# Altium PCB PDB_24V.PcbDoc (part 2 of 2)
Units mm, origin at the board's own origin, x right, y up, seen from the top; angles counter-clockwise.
Board outline 185 x 160 mm, 4 copper layers (Top Layer, Int1 (GND), Int2 (GND), Bottom Layer), stack 1.636 mm thick; 170 components, 90 nets, 598 pads, 1109 vias.
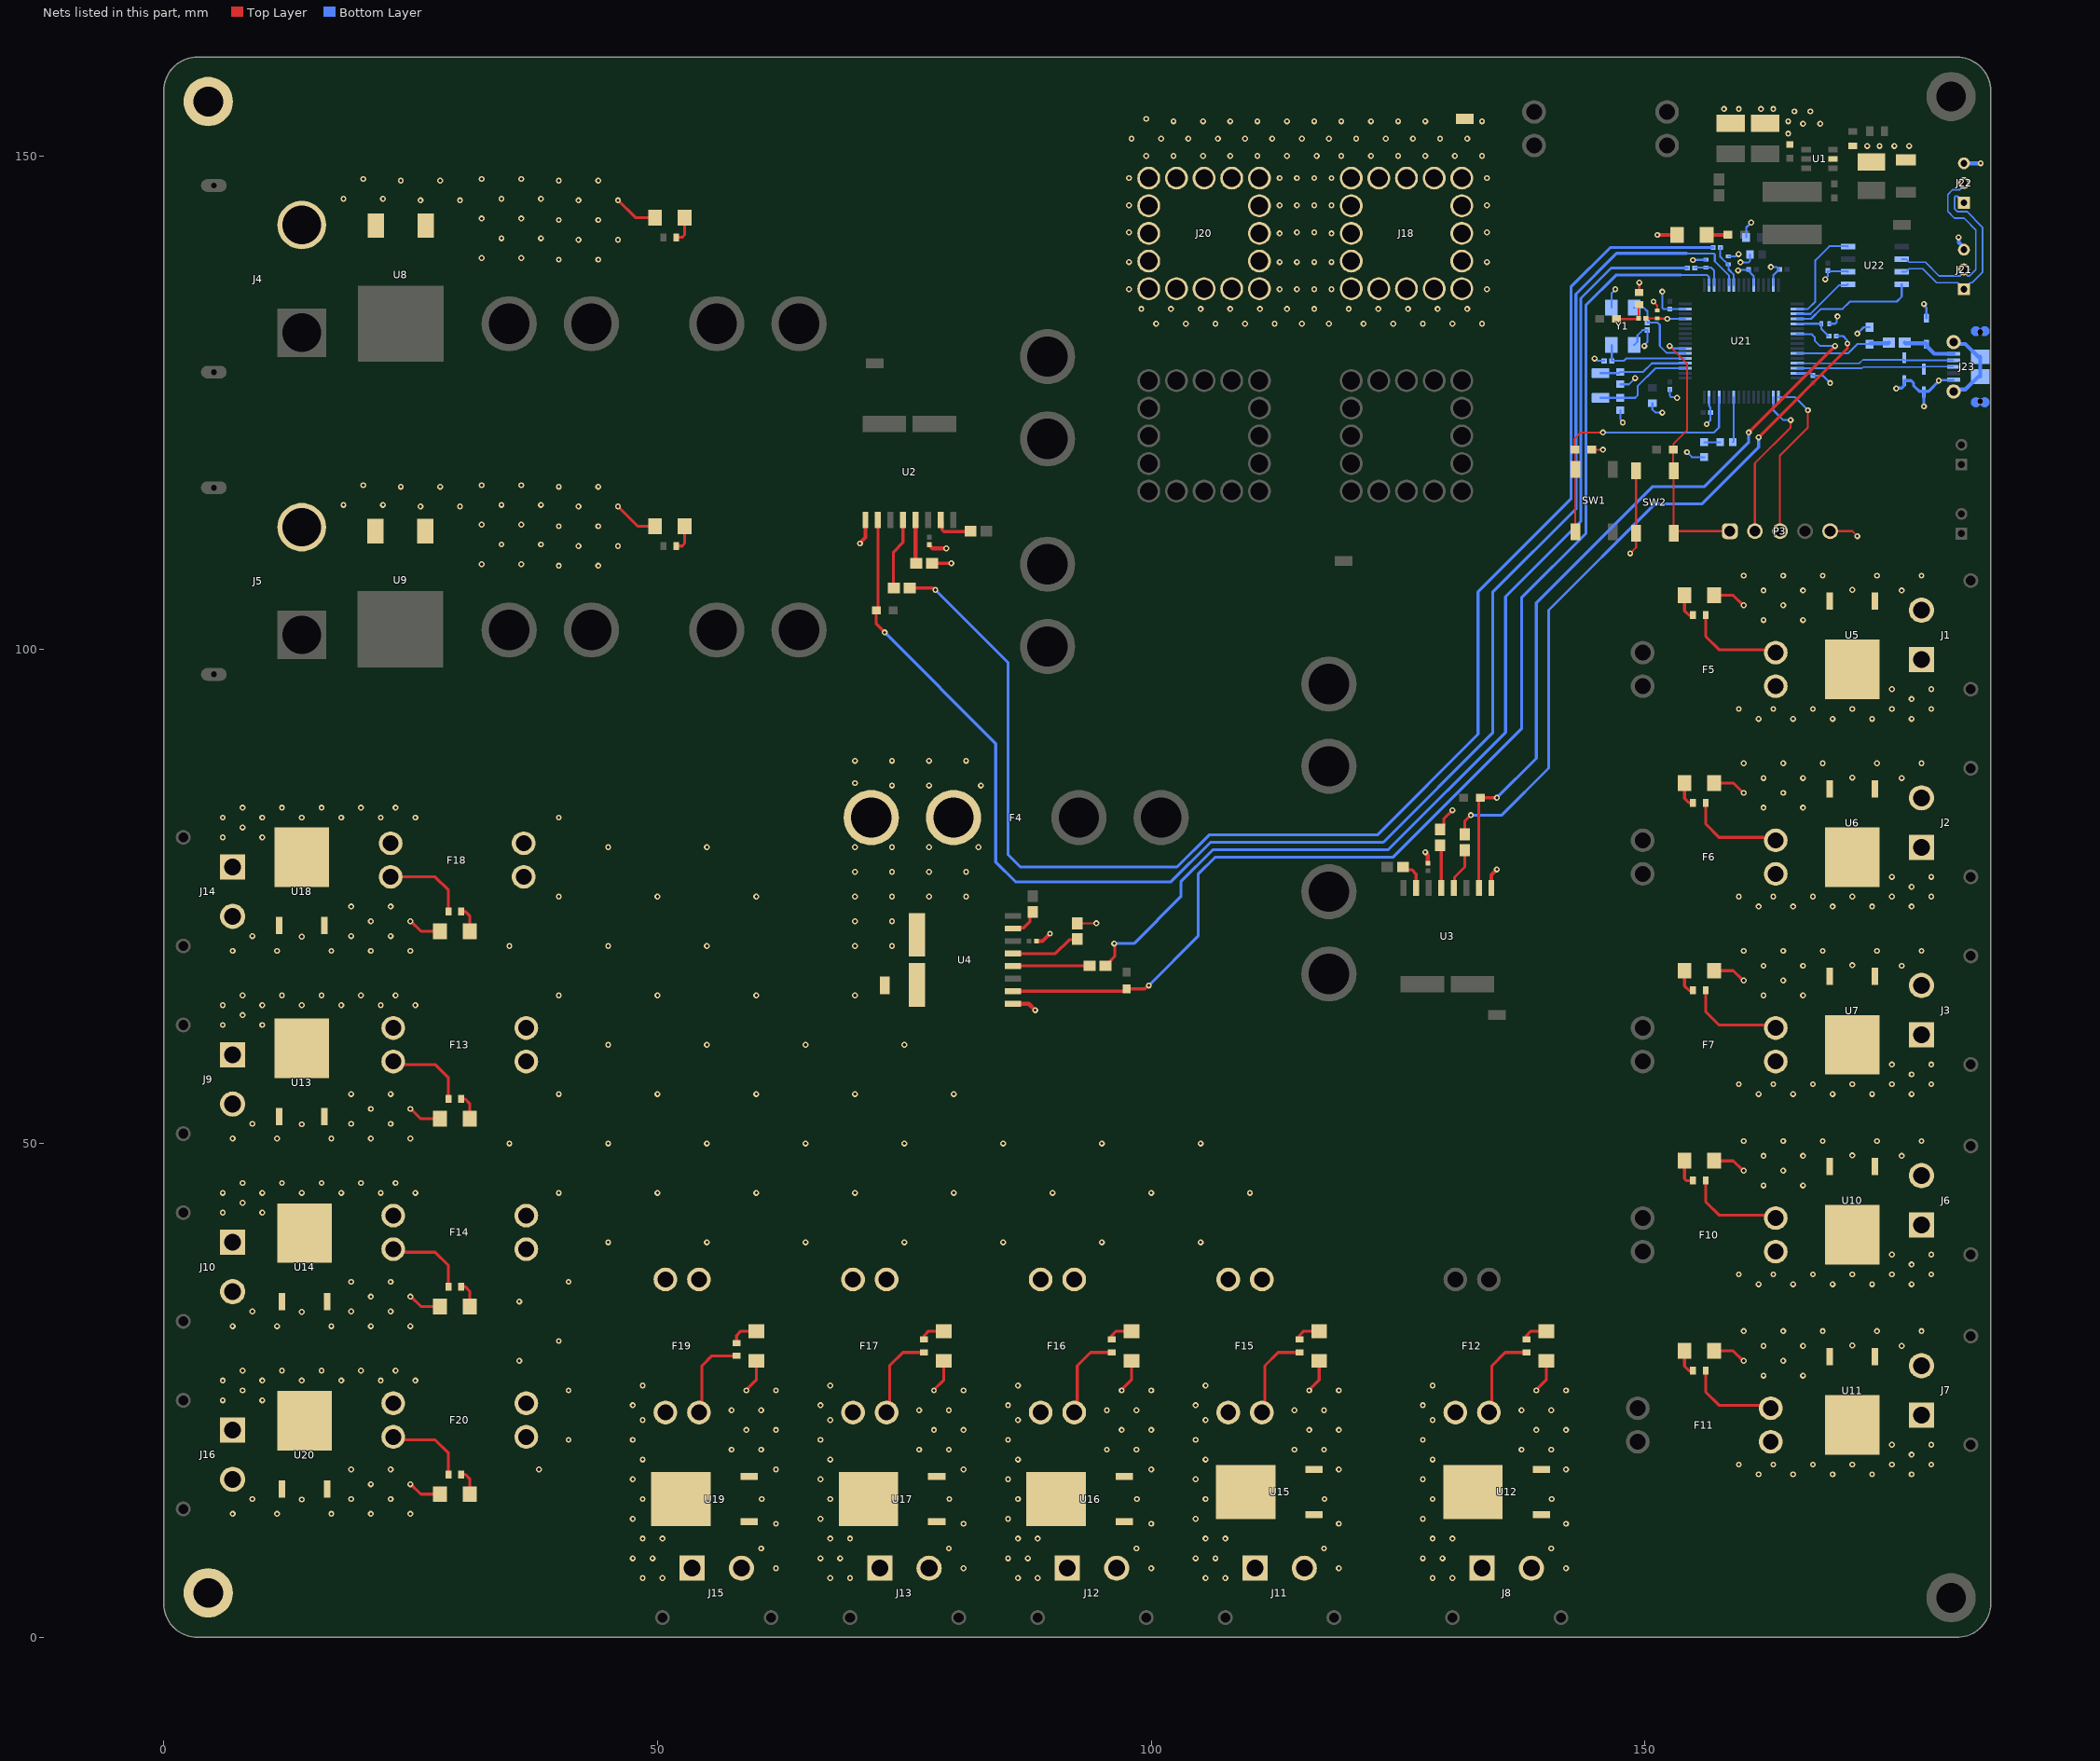
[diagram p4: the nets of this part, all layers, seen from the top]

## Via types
v1: diameter 0.6, hole 0.3, Top Layer to Bottom Layer, 1109 vias

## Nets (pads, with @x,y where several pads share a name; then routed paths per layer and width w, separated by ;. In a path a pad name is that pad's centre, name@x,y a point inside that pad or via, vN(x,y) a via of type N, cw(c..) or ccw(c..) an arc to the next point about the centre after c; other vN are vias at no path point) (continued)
24V_LIGTHING: F14.2_1 F14.2_2 J10.P R20.2 U14.3 | length 8.6
  Top Layer w0.3: F14.2_1@22.975,39 27.475,39 28.825,37.65 R20.2@28.825,35.5
  other v1: 5.975,43 9.975,43 7.975,44 5.975,45 9.975,45 13.975,45 17.975,45 21.975,45 25.475,45 7.975,46 11.975,46 15.975,46 19.975,46 23.475,46
24V_M0: F5.2_1 F5.2_2 J1.P R11.2 U5.3 | length 8.6
  Top Layer w0.3: R11.2@156.15,103.5 156.15,101.35 157.5,100 162,100
  other v1: 161.5,93 165,93 169,93 173,93 177,93 159.5,94 163,94 167,94 171,94 175,94 179,94 177,95 175,96 179,96
24V_M1: F6.2_1 F6.2_2 J2.P R12.2 U6.3 | length 8.6
  Top Layer w0.3: R12.2@156.15,84.5 156.15,82.35 157.5,81 162,81
  other v1: 161.5,74 165,74 169,74 173,74 177,74 159.5,75 163,75 167,75 171,75 175,75 179,75 177,76 175,77 179,77
24V_M2: F7.2_1 F7.2_2 J3.P R13.2 U7.3 | length 8.6
  Top Layer w0.3: R13.2@156.15,65.5 156.15,63.35 157.5,62 162,62
  other v1: 161.5,55 165,55 169,55 173,55 177,55 159.5,56 163,56 167,56 171,56 175,56 179,56 177,57 175,58 179,58
24V_M3: F10.2_1 F10.2_2 J6.P R16.2 U10.3 | length 8.6
  Top Layer w0.3: R16.2@156.15,46.25 156.15,44.1 157.5,42.75 162,42.75
  other v1: 161.5,35.75 165,35.75 169,35.75 173,35.75 177,35.75 159.5,36.75 163,36.75 167,36.75 171,36.75 175,36.75 179,36.75 177,37.75 175,38.75 179,38.75
24V_M4: F11.2_1 F11.2_2 J7.P R17.2 U11.3 | length 8.6
  Top Layer w0.3: R17.2@156.15,27 156.15,24.85 157.5,23.5 F11.2_1@162,23.5
  other v1: 161.5,16.5 165,16.5 169,16.5 173,16.5 177,16.5 159.5,17.5 163,17.5 167,17.5 171,17.5 175,17.5 179,17.5 177,18.5 175,19.5 179,19.5
24V_M5: F12.2_1 F12.2_2 J8.P R18.2 U12.3 | length 8.6
  Top Layer w0.3: F12.2_1@134.5,23 134.5,27.5 135.85,28.85 R18.2@138,28.85
  other v1: 128.5,6 130.5,6 127.5,8 129.5,8 128.5,10 130.5,10 127.5,12 128.5,14 127.5,16 128.5,18 127.5,20 128.5,22 127.5,23.5 128.5,25.5
24V_MISC_F: F4.2_1 F4.2_2 U4.1
  other v1: 70,70 73.75,70 70,72.5 73.75,72.5 70,75 73.75,75 77.5,75 81.25,75 70,77.5 73.75,77.5 77.5,77.5 81.25,77.5 70,80 73.75,80 77.5,80 82.5,80 73.75,86.25 77.5,86.25 82.75,86.25 70,86.5 70,88.75 73.75,88.75 77.5,88.75 81.25,88.75
24V_MISC_S: F13.1_1 F13.1_2 F14.1_1 F14.1_2 F15.1_1 F15.1_2 F16.1_1 F16.1_2 F17.1_1 F17.1_2 F18.1_1 F18.1_2 F19.1_1 F19.1_2 F20.1_1 F20.1_2 J29.1 U4.2
  other v1: 38,17 41,20 41,25 36,28 40,30 36,34 41,36 45,40 55,40 65,40 75,40 85,40 95,40 105,40 40,45 50,45 60,45 70,45 80,45 90,45 100,45 110,45 35,50 45,50 55,50 65,50 75,50 85,50 95,50 105,50 40,55 50,55 60,55 70,55 80,55 45,60 55,60 65,60 75,60 40,65 50,65 60,65 70,65 35,70 45,70 55,70 40,75 50,75 60,75 45,80 55,80 40,83
24V_PoE: F18.2_1 F18.2_2 J14.P R24.2 U18.3 | length 8.6
  Top Layer w0.3: F18.2_1@22.975,77 27.475,77 28.825,75.65 R24.2@28.825,73.5
  other v1: 5.975,81 9.975,81 7.975,82 5.975,83 9.975,83 13.975,83 17.975,83 21.975,83 25.475,83 7.975,84 11.975,84 15.975,84 19.975,84 23.475,84
24V_SCIENCE: F13.2_1 F13.2_2 J9.P R19.2 U13.3 | length 8.6
  Top Layer w0.3: F13.2_1@22.975,58 27.475,58 28.825,56.65 R19.2@28.825,54.5
  other v1: 5.975,62 9.975,62 7.975,63 5.975,64 9.975,64 13.975,64 17.975,64 21.975,64 25.475,64 7.975,65 11.975,65 15.975,65 19.975,65 23.475,65
24V_SPARE_1: F15.2_1 F15.2_2 J11.P R21.2 U15.3 | length 8.6
  Top Layer w0.3: F15.2_1@111.5,23 111.5,27.5 112.85,28.85 R21.2@115,28.85
  other v1: 105.5,6 107.5,6 104.5,8 106.5,8 105.5,10 107.5,10 104.5,12 105.5,14 104.5,16 105.5,18 104.5,20 105.5,22 104.5,23.5 105.5,25.5
24V_SPARE_2: F16.2_1 F16.2_2 J12.P R22.2 U16.3 | length 8.6
  Top Layer w0.3: F16.2_1@92.5,23 92.5,27.5 93.85,28.85 R22.2@96,28.85
  other v1: 86.5,6 88.5,6 85.5,8 87.5,8 86.5,10 88.5,10 85.5,12 86.5,14 85.5,16 86.5,18 85.5,20 86.5,22 85.5,23.5 86.5,25.5
24V_SPARE_3: F17.2_1 F17.2_2 J13.P R23.2 U17.3 | length 8.6
  Top Layer w0.3: F17.2_1@73.5,23 73.5,27.5 74.85,28.85 R23.2@77,28.85
  other v1: 67.5,6 69.5,6 66.5,8 68.5,8 67.5,10 69.5,10 66.5,12 67.5,14 66.5,16 67.5,18 66.5,20 67.5,22 66.5,23.5 67.5,25.5
24V_SPARE_4: F19.2_1 F19.2_2 J15.P R25.2 U19.3 | length 8.3
  Top Layer w0.3: F19.2_1@54.5,23 54.5,27.5 55.5,28.5 R25.2@57.903,28.5
  other v1: 48.5,6 50.5,6 47.5,8 49.5,8 48.5,10 50.5,10 47.5,12 48.5,14 47.5,16 48.5,18 47.5,20 48.5,22 47.5,23.5 48.5,25.5
24V_SPARE_5: F20.2_1 F20.2_2 J16.P R26.2 U20.3 | length 8.6
  Top Layer w0.3: F20.2_1@22.975,20 27.475,20 28.825,18.65 R26.2@28.825,16.5
  other v1: 5.975,24 9.975,24 7.975,25 5.975,26 9.975,26 13.975,26 17.975,26 21.975,26 25.475,26 7.975,27 11.975,27 15.975,27 19.975,27 23.475,27
ARM_ALERT: R5.1 U2.4 U21.22 | length 164.5
  Top Layer w0.3: U2.4@72.325,113.125 72.325,104.175 R5.1@72.15,104 72.15,102.6 v1(73,101.75)
  Bottom Layer w0.2: 154.2,140.125 156.958,140.125 157.075,140.008 157.075,139.325 158.5,137.9 U21.22@158.5,136.924
  Bottom Layer w0.3: v1(73,101.75) 84.25,90.5 84.25,78.5 86.25,76.5 102,76.5 106,80.5 123.5,80.5 134.575,91.575 134.575,105.825 143,114.25 143,136 147.125,140.125 154.2,140.125
ARM_SENSE: R7.2 R34.1 | length 150.9
  Top Layer w0.3: R7.2@76.051,106.25 77.868,106.25 78.06,106.057 v1(78.142,106.057)
  Bottom Layer w0.3: v1(78.142,106.057) 85.5,98.699 85.5,79.25 86.75,78 102.597,78 105.847,81.25 122.896,81.25 133.1,91.454 133.1,105.85 142.5,115.25 142.5,136.725 146.5,140.725 R34.1@156.9,140.725
ARM_SENSE_IN: C26.2 R34.2 U21.23 | length 4.4
  Bottom Layer w0.2: R34.2@157.65,140.725 157.625,140.7 157.625,139.776 158.076,139.325 158.1,139.325 158.4,139.025 C26.2@158.45,139.025 ; C26.2@158.375,139 158.466,138.909 158.466,138.5 159,137.966 U21.23@159,136.924
B3.3V_LED: D1.2 R2.2 | length 2.1
  Top Layer w0.4: D1.2@156.25,142 R2.2@158.4,142
B24_Voltage: C27.2 R36.2 U21.13 | length 4
  Top Layer w0.2: R36.2@150.1,133.55 C27.2@151.243,133.55 151.268,133.525 152.241,133.525 v1(152.265,133.501)
  Bottom Layer w0.2: v1(152.265,133.501) U21.13@154.076,133.501
B24_Voltage_In: R35.1 R36.1 R37.2 | length 3.7
  Top Layer w0.2: R35.1@147.1,133.475 R36.1@149.275,133.475 ; R36.1@149.35,133.55 R37.2@149.35,134.875 ; R36.1@149.4,133.475 R36.1@149.475,133.55 ; R37.2@149.425,134.925 R37.2@149.475,134.875
CAN_N: J21.2 J22.2 U22.6 | length 20.7
  Bottom Layer w0.172: U22.6@176,139.54 176.451,139.54 176.644,139.346 176.644,139.342 176.745,139.241 178.39,139.241 179.795,137.836 181.893,137.836 J21.2@182.3,138.242 ; J21.2@182.3,138.5 J21.2@182.3,138.242 ; J22.2@182.3,147.25 182.3,146.992 181.893,146.586 181.164,146.586 180.67,146.092 180.67,144.366 181.343,143.692 182.308,143.692 183.5,142.5 183.5,138.487 182.849,137.836 182.707,137.836 J21.2@182.3,138.242
CAN_P: J21.1 J22.1 U22.7 | length 20.6
  Bottom Layer w0.172: U22.7@176,138.27 176.451,138.27 176.644,138.464 176.644,138.468 176.745,138.569 178.112,138.569 179.517,137.164 181.685,137.164 181.786,137.063 181.786,137.014 J21.1@182.3,136.5 182.814,137.014 182.814,137.063 182.915,137.164 183.127,137.164 184.172,138.209 184.172,142.778 182.586,144.364 181.621,144.364 181.342,144.644 181.342,145.813 181.442,145.914 181.685,145.914 181.786,145.813 181.786,145.764 J22.1@182.3,145.25
CAN_RX: U21.34 U22.4 | length 10.2
  Bottom Layer w0.2: U21.34@165.424,134.501 166.501,134.501 167.25,135.25 167.25,139.434 168.666,140.85 170.512,140.85 U22.4@170.552,140.81
CAN_STB: U21.36 U22.8 | length 12.8
  Bottom Layer w0.2: U21.36@165.424,133.501 166.816,133.501 167.816,134.5 170,134.5 170.75,135.25 175.5,135.25 176,135.75 U22.8@176,137
CAN_TX: U21.35 U22.1 | length 6.4
  Bottom Layer w0.2: U21.35@165.424,134.001 166.751,134.001 169.639,136.889 170.44,136.889 U22.1@170.552,137
CHASSIS_ALERT: R6.1 U3.4 U21.39 | length 78.4
  Top Layer w0.3: U3.4@133.175,75.875 133.175,84.825 R6.1@133.35,85 v1(135,85) ; v1(160.5,122) v1(169.25,130.75)
  Bottom Layer w0.2: U21.39@165.424,132 165.464,131.96 166.091,131.96 166.112,131.94 166.877,131.94 167.184,131.633 167.184,131.316 167.75,130.75 v1(169.25,130.75)
  Bottom Layer w0.3: v1(135,85) 139,89 139,104.75 150.75,116.5 156,116.5 160.5,121 v1(160.5,122)
CHASSIS_SENSE: R8.2 R33.1 | length 72
  Top Layer w0.3: R8.2@131.75,81.301 131.75,82.635 v1(132.365,83.25) ; v1(161.5,121.5) 170.5,130.5 v1(170.5,131)
  Bottom Layer w0.2: R33.1@169.375,131.75 170.075,131.75 170.443,131.382 170.443,131.057 v1(170.5,131)
  Bottom Layer w0.3: v1(132.365,83.25) 135.5,83.25 140.25,88 140.25,104 151,114.75 155.75,114.75 161.5,120.5 v1(161.5,121.5)
CHASSIS_SENSE_IN: C25.2 R33.2 U21.37 | length 4
  Bottom Layer w0.2: U21.37@165.424,133 167.85,133 167.85,132.5 168.6,131.75 R33.2@168.625,131.75
GND: C2.2 C3.2 C4.1 C5.1 C6.1 C7.1 C8.1 C9.1 C10.1 C11.1 C12.1 C13.1 C14.1 C15.1 C16.1 C17.1 C18.1 C19.1 C20.1 C21.1 C22.1 C23.1 C24.1 C25.1 C26.1 C27.1 D1.1 D2.1 D3.1 D4.1 D5.1 D6.1 D7.1 D8.1 D9.1 D10.1 D11.1 D12.1 D13.1 D14.1 D15.1 D16.1 D17.1 D18.1 D19.2 J1.N J2.N J3.N J4.N J5.N J6.N J7.N J8.N J9.N J10.N J11.N J12.N J13.N J14.N J15.N J16.N J18.1 J18.2 J18.3 J18.4 J18.5 J18.6 J18.7 J18.8 J18.9 J18.10 J18.11 J18.12 J18.13 J18.14 J18.15 J18.16 J20.1 J20.2 J20.3 J20.4 J20.5 J20.6 J20.7 J20.8 J20.9 J20.10 J20.11 J20.12 J20.13 J20.14 J20.15 J20.16 J21.3 J22.3 J23.5 J23.6 J23.7 J23.8 J23.9 J23.10 J23.11 J25.1 P3.5 pad.2@4.5,4.5 pad.2@4.5,155.5 R4.2 R29.1 R31.1 R37.1 R38.2 R39.2 R42.2 SW2.1 SW2.2 U1.2 U2.3 U3.3 U4.3 U5.1 U5.2 U6.1 U6.2 U7.1 U7.2 U8.1 U8.2 U9.1 U9.2 U10.1 U10.2 U11.1 U11.2 U12.1 U12.2 U13.1 U13.2 U14.1 U14.2 U15.1 U15.2 U16.1 U16.2 U17.1 U17.2 U18.1 U18.2 U19.1 U19.2 U20.1 U20.2 U21.15 U21.27 U21.31 U21.47 U21.63 U22.2 U23.2 U24.2 Y1.2 Y1.4 | length 158.5
  Top Layer w0.2: R42.2@92.5,72.301 v1(94.449,72.301) ; R29.1@144.6,120.25 v1(145.75,120.25) ; v1(148.5,109.75) 149.1,110.35 SW2.1@149.1,111.8 SW2.2@149.1,118.1 ; R37.1@149.425,136.175 v1(149.425,137.175) ; v1(150.868,135.25) 150.868,135.225 151.243,134.85 C27.1@151.243,134.35 ; P3.5@168.75,112 171,112 v1(171.5,111.5)
  Top Layer w0.3: v1(24.975,15.5) 25.036,15.5 26.036,14.5 D17.1@27.975,14.5 ; v1(24.975,34.5) 25.036,34.5 26.036,33.5 D11.1@27.975,33.5 ; v1(24.975,53.5) 25.036,53.5 26.036,52.5 D10.1@27.975,52.5 ; v1(24.975,72.5) 25.036,72.5 26.036,71.5 D15.1@27.975,71.5 ; v1(46,114.5) 48,112.5 D6.1@49.75,112.5 ; v1(46,145.5) 47.75,143.75 D5.1@49.75,143.75 ; v1(59,25) 59,25.061 60,26.061 D16.1@60,28 ; R38.2@77.801,108.75 v1(79.75,108.75) ; v1(78,25) 78,25.061 79,26.061 D14.1@79,28 ; v1(97,25) 97,25.061 98,26.061 D13.1@98,28 ; v1(116,25) 116,25.061 117,26.061 D12.1@117,28 ; R39.2@129.25,81.801 129.629,82.18 129.629,82.879 v1(130.5,83.75) ; v1(139,25) 139,25.061 140,26.061 D9.1@140,28 ; D8.1@157,29 158.939,29 v1@159.939,28 ; D7.1@157,48.25 158.939,48.25 159.939,47.25 v1(160,47.25) ; D4.1@157,67.5 158.939,67.5 159.939,66.5 v1(160,66.5) ; D3.1@157,86.5 158.939,86.5 v1@159.939,85.5 ; D2.1@157,105.5 158.939,105.5 v1@159.939,104.5 ; v1@159.939,28 v1(160,28) v1@159.939,28 ; v1@159.939,85.5 v1(160,85.5) v1@159.939,85.5 ; v1@159.939,104.5 v1(160,104.5) v1@159.939,104.5
  Top Layer w0.4: v1(70.5,110.75) 70.5,110.804 71.055,111.359 U2.3@71.055,113.125 ; C7.1@77.5,110.621 77.5,110.6 77.536,110.564 77.558,110.564 77.871,110.25 v1(79.25,110.25) ; U4.3@86,64.15 87.6,64.15 v1(88.25,63.5) ; C9.1@88.379,70.5 89,70.5 v1(89.75,71.25) ; v1(127.75,79.5) 127.75,79.446 128,79.196 C8.1@128,78.379 ; U3.3@134.445,75.875 134.445,77.195 v1(135,77.75) ; v1(151.25,142) D1.1@153.25,142
  Bottom Layer w0.2: v1(144.9,129.475) 145.008,129.475 145.233,129.25 C18.1@145.86,129.25 ; Y1.4@146.6,134.65 146.6,136.051 147,136.451 v1(147,136.5) ; C20.1@147.5,124.246 147.5,123.358 147.75,123.108 v1(147.75,123) ; C19.1@147.5,126.873 148.373,126.873 v1(149,127.5) ; Y1.2@148.9,130.85 149.233,131.183 149.233,131.833 149.76,132.36 C17.1@150.25,132.36 150.25,131.176 149.933,130.858 v1(149.933,130.75) ; C11.1@150.75,124.975 150.75,124.325 151.05,124.025 151.725,124.025 v1(151.75,124) ; v1(151.75,136.25) 151.75,134.61 151.867,134.493 C16.1@152.5,134.493 152.504,134.497 154.072,134.497 U21.15@154.076,134.501 ; C12.1@152.5,126.348 152.5,125.724 152.65,125.574 153.176,125.574 v1(153.25,125.5) ; v1(154.25,120) 154.75,119.5 D18.1@156,119.5 ; v1(154.85,139.45) 154.875,139.475 156.15,139.475 C24.1@156.175,139.5 ; v1(156.25,122.841) 156.629,123.22 C13.1@156.629,124 156.629,124.536 156.499,124.666 U21.63@156.499,125.576 ; C26.1@158.45,139.825 159.192,139.825 159.417,140.05 v1(159.475,140.05) ; v1(159.425,138.4) 159.475,138.45 160.443,138.45 C23.1@160.493,138.5 ; v1(159.675,139.225) 160.508,139.225 160.625,139.342 C22.1@160.625,140 ; C21.1@160.25,141.75 160.25,142.75 v1(160.75,143.25) ; C23.1@160.514,138.5 160.651,138.364 160.651,138.181 160.868,137.964 160.883,137.964 161,137.847 U21.27@161,136.924 ; v1(162.75,138.75) 163.35,138.75 C15.1@163.6,138.5 ; U21.31@163.001,136.924 163.001,137.901 C15.1@163.6,138.5 ; C15.1@163.621,138.5 C15.1@163.6,138.5 ; U21.47@165.424,127.999 166.779,127.999 167,127.779 C14.1@167,127.757 167.993,127.757 v1(168.75,127) ; v1(168.25,137.5) 168.25,137.564 168.5,137.814 C10.1@168.5,138.371 168.551,138.321 170.501,138.321 U22.2@170.552,138.27 ; C25.1@168.65,133 169.25,133 169.423,133.173 169.423,133.673 v1(169.5,133.75) ; v1(171.5,132) 172.15,132.65 R31.1@172.75,132.65 ; v1(178.25,135) 178.25,134.892 178.5,134.642 D19.2@178.5,133.55 ; v1(179.75,127.25) 179.8,127.3 181.2,127.3 J23.5@181.25,127.35
  Bottom Layer w0.3: v1(175.44,126.44) 175.498,126.498 176.024,126.498 176.2,126.674 U23.2@176.2,126.895 ; U23.2@176.25,126.895 U23.2@176.25,127.25 176.95,127.25 177.203,126.997 177.203,126.732 177.775,126.16 178.2,126.16 U24.2@178.25,126.109 ; v1(178.25,124.627) U24.2@178.25,126.109 ; U24.2@178.25,126.1 U24.2@178.25,126.109 ; v1(179.75,127.25) 179.75,127.185 178.725,126.16 178.3,126.16 U24.2@178.25,126.109
  Bottom Layer w0.4: J23.7@181.25,126.15 181.451,126.351 182.451,126.351 183.75,127.65 J23.10@183.95,127.65 J23.9@183.95,129.65 183.75,129.65 182.451,130.949 181.451,130.949 J23.6@181.25,131.15 ; v1(181.75,141.75) 181.788,141.712 181.788,141.228 182.3,140.716 J21.3@182.3,140.5 ; J22.3@182.3,149.25 v1(184,149.25)
  other v1: 62,7 81,7 100,7 119,7 142,7 60.5,9 79.5,9 98.5,9 117.5,9 140.5,9 62,11.5 81,11.5 100,11.5 119,11.5 142,11.5 6.975,12.5 11.475,12.5 16.975,12.5 20.975,12.5 24.975,12.5 13.975,13.95 8.975,14 18.975,14 22.975,14 60.55,14 79.55,14 98.55,14 117.55,14 140.55,14 20.975,15.5 18.975,17 22.975,17 62,17 81,17 100,17 119,17 142,17 57.5,19 60.5,19 76.5,19 79.5,19 95.5,19 98.5,19 114.5,19 117.5,19 137.5,19 140.5,19 59,21 62,21 78,21 81,21 97,21 100,21 116,21 119,21 139,21 142,21 57.5,23 60.5,23 76.5,23 79.5,23 95.5,23 98.5,23 114.5,23 117.5,23 137.5,23 140.5,23 62,25 81,25 100,25 119,25 142,25 162,26.5 166,26.5 164,28 162,29.5 166,29.5 176,29.5 171,29.55 160,31 164,31 168,31 173.5,31 178,31 6.975,31.5 11.475,31.5 16.975,31.5 20.975,31.5 24.975,31.5 13.975,32.95 8.975,33 18.975,33 22.975,33 20.975,34.5 18.975,36 22.975,36 162,45.75 166,45.75 164,47.25 162,48.75 166,48.75 176,48.75 171,48.8 160,50.25 164,50.25 168,50.25 173.5,50.25 178,50.25 6.975,50.5 11.475,50.5 16.975,50.5 20.975,50.5 24.975,50.5 13.975,51.95 8.975,52 18.975,52 22.975,52 20.975,53.5 18.975,55 22.975,55 162,65 166,65 164,66.5 162,68 166,68 176,68 171,68.05 6.975,69.5 11.475,69.5 16.975,69.5 20.975,69.5 24.975,69.5 160,69.5 164,69.5 168,69.5 173.5,69.5 178,69.5 13.975,70.95 8.975,71 18.975,71 22.975,71 20.975,72.5 18.975,74 22.975,74 162,84 166,84 164,85.5 162,87 166,87 176,87 171,87.05 160,88.5 164,88.5 168,88.5 173.5,88.5 178,88.5 162,103 166,103 164,104.5 162,106 166,106 176,106 171,106.05 160,107.5 164,107.5 168,107.5 173.5,107.5 178,107.5 40,108.5 44,108.5 32.197,108.657 36.197,108.657 42,110.5 46,110.5 34.197,110.657 38.197,110.657 40,112.5 44,112.5 32.197,112.657 36.197,112.657 26,114.5 30,114.5 42,114.5 18.197,114.657 22.197,114.657 34.197,114.657 38.197,114.657 24,116.5 28,116.5 40,116.5 44,116.5 20.197,116.657 32.197,116.657 36.197,116.657 100.5,133 103.5,133 106.5,133 109.5,133 112.5,133 115.25,133 118,133 121.5,133 124.5,133 127.5,133 130.5,133 133.5,133 99,134.5 102,134.5 105,134.5 108,134.5 111,134.5 113.75,134.5 116.5,134.5 120,134.5 123,134.5 126,134.5 129,134.5 132,134.5 97.75,136.5 113,136.5 114.75,136.5 116.5,136.5 118.25,136.5 134,136.5 97.75,139.25 113,139.25 114.75,139.25 116.5,139.25 118.25,139.25 134,139.25 40,139.5 44,139.5 32.197,139.657 36.197,139.657 42,141.5 46,141.5 34.197,141.657 38.197,141.657 113,142.15 118.25,142.15 97.75,142.25 114.75,142.25 116.5,142.25 134,142.25 40,143.5 44,143.5 32.197,143.657 36.197,143.657 97.75,145 113,145 114.75,145 116.5,145 118.25,145 134,145 26,145.5 30,145.5 42,145.5 18.197,145.657 22.197,145.657 34.197,145.657 38.197,145.657 24,147.5 28,147.5 40,147.5 44,147.5 20.197,147.657 32.197,147.657 36.197,147.657 97.75,147.75 113,147.75 114.75,147.75 116.5,147.75 118.25,147.75 134,147.75 99.5,150 102.25,150 105.25,150 108,150 110.75,150 113.75,150 116.75,150 119.25,150 122.25,150 125,150 127.75,150 130.75,150 133.5,150 172.5,151 173.75,151 175.25,151 176.75,151 98,151.75 101,151.75 103.75,151.75 106.75,151.75 109.5,151.75 112.25,151.75 115.25,151.75 118,151.75 120.75,151.75 123.75,151.75 126.5,151.75 129.25,151.75 132,151.75 164.5,152.25 166,153.25 167.75,153.25 102.25,153.5 105.25,153.5 108,153.5 110.75,153.5 113.75,153.5 116.5,153.5 119.25,153.5 122.25,153.5 125,153.5 127.75,153.5 133.5,153.5 164.5,153.5 99.5,153.75 165.125,154.5 166.75,154.5 158,154.75 159.5,154.75 161.75,154.75 163,154.75
HSE_OSC_IN: C18.2 U21.5 Y1.3 | length 9.2
  Bottom Layer w0.2: Y1.3@146.6,130.85 146.64,130.81 C18.2@146.64,129.25 147.875,129.25 148.125,129.5 U21.5@154.076,129.5
HSE_OSC_OUT: C17.2 U21.6 Y1.1 | length 9
  Bottom Layer w0.2: Y1.1@148.9,134.65 149.85,134.65 150.25,134.25 C17.2@150.25,133.14 151.243,133.14 151.5,132.883 151.5,130.75 152.211,130.039 154.036,130.039 U21.6@154.076,130
LED_DEBUG_1: D18.2 R27.1 | length 1.6
  Bottom Layer w0.2: D18.2@156,121 R27.1@157.623,121
LED_DEBUG_2: R27.2 U21.58 | length 4.6
  Bottom Layer w0.2: R27.2@158.877,121 159,121.123 U21.58@159,125.576
LSE_OSC_IN: C20.2 U21.3 Y2.2 | length 10.4
  Bottom Layer w0.2: Y2.2@145.5,125.5 C20.2@147.5,125.5 149,125.5 149.25,125.75 149.25,126.689 151.061,128.499 U21.3@154.076,128.499
LSE_OSC_OUT: C19.2 U21.4 Y2.1 | length 9
  Bottom Layer w0.2: Y2.1@145.5,128 147.373,128 C19.2@147.5,128.127 149.811,128.127 150.684,128.999 U21.4@154.076,128.999
MCU_BOOT0: R29.2 SW1.1 SW1.2 U21.61 | length 27.6
  Top Layer w0.2: SW1.1@142.95,111.95 SW1.2@142.95,118.25 142.95,120.15 142.85,120.25 142.85,121.35 143.5,122 v1(145.75,122)
  Bottom Layer w0.2: v1(145.75,122) 157,122 157.499,122.499 U21.61@157.499,125.576
MCU_NRST: P3.1 R28.1 SW2.3 SW2.4 U21.7 | length 27.7
  Top Layer w0.2: v1(152.5,130.75) 154.251,128.999 154.251,122.201 152.883,120.833 152.883,120.283 R28.1@152.85,120.25 152.85,118.15 SW2.4@152.9,118.1 SW2.3@152.9,111.8 153.1,112 P3.1@158.59,112
  Bottom Layer w0.2: v1(152.5,130.75) 152.608,130.75 152.858,130.5 U21.7@154.076,130.5
MISC_ALERT: R9.1 U4.4 U21.18 | length 126.4
  Top Layer w0.3: U4.4@86,65.42 97.3,65.42 97.5,65.62 R9.1@97.5,65.65 99.346,65.65 99.696,66 v1(99.75,66)
  Bottom Layer w0.2: 153.625,137.925 156.3,137.925 156.483,137.742 156.483,136.94 U21.18@156.499,136.924
  Bottom Layer w0.3: v1(99.75,66) 104.75,71 104.75,77.25 106.5,79 124.5,79 137.5,92 137.5,105.25 144.025,111.775 144.025,134.899 147.051,137.925 153.625,137.925
MISC_SENSE: R10.2 R32.1 | length 111.3
  Top Layer w0.3: R10.2@95.352,68 95.426,68 95.805,68.379 95.805,68.453 96.307,68.955 96.307,70.193 v1(96.25,70.25)
  Bottom Layer w0.3: v1(96.25,70.25) 98.25,70.25 103,75 103,76.5 106.25,79.75 124,79.75 135.875,91.625 135.875,105.375 143.5,113 143.5,135.575 146.575,138.65 R32.1@154.3,138.65
MISC_SENSE_IN: C24.2 R32.2 U21.19 | length 3.6
  Bottom Layer w0.2: R32.2@155.05,138.65 155.075,138.675 156.15,138.675 C24.2@156.175,138.7 156.675,138.7 156.999,138.376 U21.19@156.999,136.924
NetD2_2: D2.2 R11.1 | length 2.6
  Top Layer w0.3: D2.2@154,105.5 154,103.95 154.45,103.5 R11.1@154.85,103.5
NetD3_2: D3.2 R12.1 | length 2.6
  Top Layer w0.3: D3.2@154,86.5 154,84.95 154.45,84.5 R12.1@154.85,84.5
NetD4_2: D4.2 R13.1 | length 2.6
  Top Layer w0.3: D4.2@154,67.5 154,65.95 154.45,65.5 R13.1@154.85,65.5
NetD5_2: D5.2 R14.1 | length 2.7
  Top Layer w0.3: R14.1@51.9,141.75 52.5,141.75 52.75,142 D5.2@52.75,143.75
NetD6_2: D6.2 R15.1 | length 2.7
  Top Layer w0.3: R15.1@51.9,110.5 52.5,110.5 52.75,110.75 D6.2@52.75,112.5
NetD7_2: D7.2 R16.1 | length 2.7
  Top Layer w0.3: D7.2@154,48.25 154,46.426 154.176,46.25 R16.1@154.85,46.25
NetD8_2: D8.2 R17.1 | length 2.6
  Top Layer w0.3: D8.2@154,29 154,27.45 154.45,27 R17.1@154.85,27
NetD9_2: D9.2 R18.1 | length 2.6
  Top Layer w0.3: R18.1@138,30.15 138,30.55 138.45,31 D9.2@140,31
NetD10_2: D10.2 R19.1 | length 2.6
  Top Layer w0.3: R19.1@30.125,54.5 30.525,54.5 30.975,54.05 D10.2@30.975,52.5
NetD11_2: D11.2 R20.1 | length 2.6
  Top Layer w0.3: R20.1@30.125,35.5 30.525,35.5 30.975,35.05 D11.2@30.975,33.5
NetD12_2: D12.2 R21.1 | length 2.6
  Top Layer w0.3: R21.1@115,30.15 115,30.55 115.45,31 D12.2@117,31
NetD13_2: D13.2 R22.1 | length 2.6
  Top Layer w0.3: R22.1@96,30.15 96,30.55 96.45,31 D13.2@98,31
NetD14_2: D14.2 R23.1 | length 2.6
  Top Layer w0.3: R23.1@77,30.15 77,30.55 77.45,31 D14.2@79,31
NetD15_2: D15.2 R24.1 | length 2.6
  Top Layer w0.3: R24.1@30.125,73.5 30.525,73.5 30.975,73.05 D15.2@30.975,71.5
NetD16_2: D16.2 R25.1 | length 2.9
  Top Layer w0.3: R25.1@58,29.792 58,30.55 58.45,31 D16.2@60,31
NetD17_2: D17.2 R26.1 | length 2.6
  Top Layer w0.3: R26.1@30.125,16.5 30.525,16.5 30.975,16.05 D17.2@30.975,14.5
NetR7_1: R7.1 U2.6 | length 7.3
  Top Layer w0.3: R7.1@73.898,106.25 73.898,109.898 74.865,110.865 U2.6@74.865,113.125
NetR8_1: R8.1 U3.6 | length 4.2
  Top Layer w0.3: U3.6@130.635,75.875 130.711,75.951 130.711,76.961 131.75,78 R8.1@131.75,79.564
NetR10_1: R10.1 U4.6 | length 7.8
  Top Layer w0.3: U4.6@86,67.96 86.02,67.98 R10.1@93.75,67.98
NetR38_1: R38.1 U2.7 | length 4.4
  Top Layer w0.4: U2.7@76.135,113.125 76.135,108.814 R38.1@76.199,108.75
NetR39_1: R39.1 U3.7 | length 4.3
  Top Layer w0.3: U3.7@129.365,75.875 R39.1@129.365,80.199
NetR40_2: R40.2 U2.9 | length 4
  Top Layer w0.3: U2.9@78.675,113.125 78.825,112.975 78.825,112.126 79.001,111.95 81.649,111.95 R40.2@81.699,112
NetR41_2: R41.2 U3.9 | length 3
  Top Layer w0.3: R41.2@125.5,78 125.774,77.726 126.377,77.726 126.825,77.278 U3.9@126.825,75.875
NetR42_1: R42.1 U4.7 | length 7.1
  Top Layer w0.3: U4.7@86,69.23 90.301,69.23 91.697,70.626 92.427,70.626 R42.1@92.5,70.699
NetR43_2: R43.2 U4.9 | length 3.1
  Top Layer w0.3: U4.9@86,71.77 86.078,71.848 87.084,71.848 87.726,72.49 87.726,73.175 R43.2@88,73.449
SWD_SWCLK: P3.2 U21.50 | length 16.2
  Top Layer w0.2: P3.2@161.13,112 161.13,118.88 164.75,122.5 v1(164.75,123.25)
  Bottom Layer w0.2: U21.50@163.001,125.576 163.001,124.249 164,123.25 v1(164.75,123.25)
SWD_SWDIO: P3.3 U21.49 | length 17
  Top Layer w0.2: P3.3@163.67,112 163.67,119.67 166.5,122.5 v1(166.5,124.25)
  Bottom Layer w0.2: U21.49@163.501,125.576 165.174,125.576 v1(166.5,124.25)
USB_D_N: J23.2 U21.45 U23.1 | length 16
  Bottom Layer w0.148: U21.45@165.424,128.999 171.714,128.999 172.064,129.35 174.25,129.35 176,129.35 176.25,129.35 176.3,129.3 176.5,129.3 176.75,129.3 J23.2@181.25,129.3
USB_D_P: J23.3 U21.46 U24.1 | length 15.9
  Bottom Layer w0.148: U21.46@165.424,128.499 171.964,128.499 172.065,128.6 178.25,128.6 178.3,128.65 J23.3@181.25,128.65
VBUS: D19.1 J23.1 R30.2 | length 5.6
  Bottom Layer w0.4: R30.2@176.301,131.1 176.376,131.025 178.45,131.025 178.5,130.975 D19.1@178.5,130.95 178.5,130.75 179.3,129.95 J23.1@181.25,129.95
VBUS_SENSE: R30.1 R31.2 U21.43 | length 9.7
  Bottom Layer w0.2: U21.43@165.424,130 170.55,130 171.5,130.95 R31.2@172.75,130.95 R31.2@172.825,131.025
  Bottom Layer w0.4: R31.2@172.825,131.025 174.624,131.025 R30.1@174.699,131.1
pads on no net: J1.S1 J1.S2 J2.S1 J2.S2 J3.S1 J3.S2 J4.S1 J4.S2 J5.S1 J5.S2 J6.S1 J6.S2 J7.S1 J7.S2 J8.S1 J8.S2 J9.S1 J9.S2 J10.S1 J10.S2 J11.S1 J11.S2 J12.S1 J12.S2 J13.S1 J13.S2 J14.S1 J14.S2 J15.S1 J15.S2 J16.S1 J16.S2 J23.4 U2.5 U2.10 U3.5 U3.10 U4.5 U4.10 U21.2 U21.8 U21.9 U21.10 U21.11 U21.12 U21.14 U21.17 U21.20 U21.21 U21.24 U21.25 U21.26 U21.30 U21.33 U21.38 U21.40 U21.41 U21.42 U21.44 U21.51 U21.56 U21.57 U21.59 U21.60 U21.62 U22.5

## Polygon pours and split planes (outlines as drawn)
24V_BUCK on Top Layer "GND_L02_P-001" (solid, remove dead copper, pour order 171): 151,156.75 155.75,156.75 156.25,156.25 156.25,151.25 151,151.25
24V_BUCK on Top Layer "GND_L02_P-001" (solid, remove dead copper, pour order 126): 167,149.7 167,149.5 166.75,149.25 161.25,149.25 160,148 160,147.5 159.5,147 155.75,147 155.25,146.5 155.25,145 154.75,144.5 150.5,144.5 150,145 150,156.25 150.5,156.75 154.546,156.75 154.546,151.25 163.5,151.25 164.5,150.25 166.75,150.25 167,150 167,149.9 167,149.75
24V on Top Layer "GND_L02_P-001" (solid, remove dead copper, pour order 163): 97,130 98.25,131.25 133.75,131.25 135,130 135,110 131.75,106.75 131.75,92 122.25,82.5 105.75,82.5 103,79.75 87.75,79.75 86.25,81.25 86.25,112.5 87.5,113.75 95.5,113.75 97,115.25
GND on Top Layer "GND_L02_P-001" (solid, remove dead copper, pour order 164): 98.25,132.5 97,133.75 97,153.75 98.5,155.25 133.75,155.25 135,154 135,133.75 133.75,132.5
24V on Top Layer "GND_L02_P-001" (solid, remove dead copper, pour order 165): 133.75,131.25 136.25,133.75 136.25,156.5 137.5,157.75 140.25,157.75 141.5,156.5 141.5,116.5 135,110
24V_M4 on Top Layer "GND_L02_P-001" (solid, remove dead copper, pour order 62): 179.5,25 180.5,24 180.5,16.5 179.5,15.5 159.5,15.5 158.5,16.5 158.5,24 159.5,25
GND on Top Layer "GND_L02_P-001" (solid, remove dead copper, pour order 63): 159.5,25.5 158.5,26.5 158.5,31.5 159.5,32.5 179.5,32.5 180.5,31.667 180.5,26.5 179.5,25.5
24V_M3 on Top Layer "GND_L02_P-001" (solid, remove dead copper, pour order 65): 179.5,44.25 180.5,43.25 180.5,35.75 179.5,34.75 159.5,34.75 158.5,35.75 158.5,43.25 159.5,44.25
GND on Top Layer "GND_L02_P-001" (solid, remove dead copper, pour order 66): 159.5,44.75 158.5,45.75 158.5,50.75 159.5,51.75 179.5,51.75 180.5,50.917 180.5,45.75 179.5,44.75
24V_CHASSIS_S on Top Layer "GND_L02_P-001" (solid, remove dead copper, pour order 118): 130.25,52.5 127.75,50 127.75,35.5 129.25,34 150.75,34 152.25,35 152.25,102.5 151.25,103.5 142.75,103.5 141.25,102 141.25,69 140,67.75 130.75,67.75 130.25,67.25
24V_CHASSIS_F on Top Layer "GND_L02_P-001" (solid, remove dead copper, pour order 155): 129.75,67.25 129.25,67.75 127.25,67.75 122.5,72.5 122.5,77.75 121.75,78.5 106.75,78.5 106,77.75 106,57.5 107.5,56 129.25,56 129.75,56.5
24V_MISC_F on Top Layer "GND_L02_P-001" (solid, remove dead copper, pour order 151): 78.5,69 70,69 67.5,71.5 67.5,88.75 68.75,90 82.5,90 83.75,88.75 83.75,74.25
24V_ARM_F on Top Layer "GND_L02_P-001" (solid, remove dead copper, pour order 149): 75.75,135.5 79,138.75 95,138.75 96.25,137.5 96.25,119 95,117.5 77.25,117.5 75.75,119
24V_ARM_S on Top Layer "GND_L02_P-001" (solid, remove dead copper, pour order 122): 52.5,92.5 54,91 67.5,91 69,92.5 69,118.75 70.75,120.5 74.5,120.5 75.25,121.25 75.25,128.5 65,138.75 54.5,138.75 52.5,136.75 52.5,116.5 55,114 55,110.75 52.5,108.25
24V_CHASSIS_S on Top Layer "GND_L02_P-001" (solid, remove dead copper, pour order 121): 152.25,35 152.25,17.25 151.25,16.25 146.25,16.25 145.25,17.25 145.25,33 143.25,35 143,35
24V_MISC_S on Top Layer "GND_L02_P-001" (solid, remove dead copper, pour order 113): 113.25,33.75 35,33.75 33.75,35 33.75,84
24V_MISC_S on Top Layer "GND_L02_P-001" (solid, remove dead copper, pour order 111): 33.75,84 34.75,85 52,85 68.5,68.5 78.5,68.5 79,68 79,62.5 89,52.5 112,52.5 113.75,50.75 113.75,34.25 113.25,33.75
GND on Top Layer "GND_L02_P-001" (solid, remove dead copper, pour order 130): 157.25,152.25 157,152.5 157,155 157.25,155.25 165,155.25 165.25,155 165.25,151 165,150.75 164.25,150.75 162.75,152.25
GND on Top Layer "GND_L02_P-001" (solid, remove dead copper, pour order 131): 167,152.5 167.25,152.25 167.25,149.5 167.5,149.25 170.5,149.25 170.75,149 170.75,148.226 171.026,147.95 177.95,147.95 178.25,148.25 178.25,151.5 178,151.75 170.5,151.75 170.25,151.5 170.25,150.25 170,150 168.5,150 168.25,150.25 168.25,155 168,155.25 165,155.25 165,152.5
3V3_SW on Top Layer "GND_L02_P-001" (solid, remove dead copper, pour order 132): 166.488,149.004 166.485,149 162.25,149 161.75,148.5 161.75,145 162.25,144.5 169.5,144.5 170,145 170,146.276 169.826,146.45 168.451,146.45 168.451,147.549 166.754,149.004 166.504,149.004
3.3V on Top Layer "GND_L02_P-001" (solid, remove dead copper, pour order 134): 171,147.5 170.75,147.25 170.75,144.25 170,143.5 162.25,143.5 161.75,143 161.75,140.25 162.25,139.75 177.5,139.75 177.95,140.2 177.95,147.3 177.75,147.5
24V_MISC_S on Top Layer "GND_L02_P-001" (solid, remove dead copper, pour order 117): 33.75,35 33.75,17.25 35,16 41.5,16 42.75,17.25 42.75,32.75 45,35
GND on Top Layer "GND_L02_P-001" (solid, remove dead copper, pour order 107): 10.5,138.5 9,140 9,147 10.5,148.5 46.5,148.5 48,147 48,140 46.5,138.5
24V_ARM1 on Top Layer "GND_L02_P-001" (solid, remove dead copper, pour order 106): 10.5,138 9,136.5 9,123.5 10.5,122 46.5,122 48,123.5 48,136.5 46.5,138
24V_ARM2 on Top Layer "GND_L02_P-001" (solid, remove dead copper, pour order 101): 10.5,107 9,105.5 9,92.5 10.5,91 46.5,91 48,92.5 48,105.5 46.5,107
GND on Top Layer "GND_L02_P-001" (solid, remove dead copper, pour order 103): 10.5,107.5 9,109 9,116 10.5,117.5 46.5,117.5 48,116 48,109 46.5,107.5
GND on Top Layer "GND_L02_P-001" (solid, remove dead copper, pour order 57): 113.5,25.5 114.5,26.5 119.5,26.5 120.5,25.5 120.5,5.5 119.667,4.5 114.5,4.5 113.5,5.5
24V_SPARE_1 on Top Layer "GND_L02_P-001" (solid, remove dead copper, pour order 56): 113,5.5 112,4.5 104.5,4.5 103.5,5.5 103.5,25.5 104.5,26.5 112,26.5 113,25.5
GND on Top Layer "GND_L02_P-001" (solid, remove dead copper, pour order 54): 94.5,25.5 95.5,26.5 100.5,26.5 101.5,25.5 101.5,5.5 100.667,4.5 95.5,4.5 94.5,5.5
24V_SPARE_2 on Top Layer "GND_L02_P-001" (solid, remove dead copper, pour order 53): 94,5.5 93,4.5 85.5,4.5 84.5,5.5 84.5,25.5 85.5,26.5 93,26.5 94,25.5
GND on Top Layer "GND_L02_P-001" (solid, remove dead copper, pour order 51): 75.5,25.5 76.5,26.5 81.5,26.5 82.5,25.5 82.5,5.5 81.667,4.5 76.5,4.5 75.5,5.5
24V_SPARE_3 on Top Layer "GND_L02_P-001" (solid, remove dead copper, pour order 50): 75,5.5 74,4.5 66.5,4.5 65.5,5.5 65.5,25.5 66.5,26.5 74,26.5 75,25.5
GND on Top Layer "GND_L02_P-001" (solid, remove dead copper, pour order 48): 56.5,25.5 57.5,26.5 62.5,26.5 63.5,25.5 63.5,5.5 62.667,4.5 57.5,4.5 56.5,5.5
24V_SPARE_4 on Top Layer "GND_L02_P-001" (solid, remove dead copper, pour order 47): 56,5.5 55,4.5 47.5,4.5 46.5,5.5 46.5,25.5 47.5,26.5 55,26.5 56,25.5
24V_PoE on Top Layer "GND_L02_P-001" (solid, remove dead copper, pour order 0): 5.475,75.5 4.475,76.5 4.475,84 5.475,85 25.475,85 26.475,84 26.475,76.5 25.475,75.5
GND on Top Layer "GND_L02_P-001" (solid, remove dead copper, pour order 14): 25.475,75 26.475,74 26.475,69 25.475,68 5.475,68 4.475,68.833 4.475,74 5.475,75
24V_SCIENCE on Top Layer "GND_L02_P-001" (solid, remove dead copper, pour order 77): 5.475,56.5 4.475,57.5 4.475,65 5.475,66 25.475,66 26.475,65 26.475,57.5 25.475,56.5
GND on Top Layer "GND_L02_P-001" (solid, remove dead copper, pour order 78): 25.475,56 26.475,55 26.475,50 25.475,49 5.475,49 4.475,49.833 4.475,55 5.475,56
24V_LIGTHING on Top Layer "GND_L02_P-001" (solid, remove dead copper, pour order 80): 5.475,37.5 4.475,38.5 4.475,46 5.475,47 25.475,47 26.475,46 26.475,38.5 25.475,37.5
GND on Top Layer "GND_L02_P-001" (solid, remove dead copper, pour order 81): 25.475,37 26.475,36 26.475,31 25.475,30 5.475,30 4.475,30.833 4.475,36 5.475,37
24V_SPARE_5 on Top Layer "GND_L02_P-001" (solid, remove dead copper, pour order 83): 5.475,18.5 4.475,19.5 4.475,27 5.475,28 25.475,28 26.475,27 26.475,19.5 25.475,18.5
GND on Top Layer "GND_L02_P-001" (solid, remove dead copper, pour order 84): 25.475,18 26.475,17 26.475,12 25.475,11 5.475,11 4.475,11.833 4.475,17 5.475,18
GND on Top Layer "GND_L02_P-001" (solid, remove dead copper, pour order 75): 159.5,102 158.5,103 158.5,108 159.5,109 179.5,109 180.5,108.167 180.5,103 179.5,102
24V_M0 on Top Layer "GND_L02_P-001" (solid, remove dead copper, pour order 74): 179.5,101.5 180.5,100.5 180.5,93 179.5,92 159.5,92 158.5,93 158.5,100.5 159.5,101.5
GND on Top Layer "GND_L02_P-001" (solid, remove dead copper, pour order 72): 159.5,83 158.5,84 158.5,89 159.5,90 179.5,90 180.5,89.167 180.5,84 179.5,83
24V_M1 on Top Layer "GND_L02_P-001" (solid, remove dead copper, pour order 71): 179.5,82.5 180.5,81.5 180.5,74 179.5,73 159.5,73 158.5,74 158.5,81.5 159.5,82.5
GND on Top Layer "GND_L02_P-001" (solid, remove dead copper, pour order 69): 159.5,64 158.5,65 158.5,70 159.5,71 179.5,71 180.5,70.167 180.5,65 179.5,64
24V_M2 on Top Layer "GND_L02_P-001" (solid, remove dead copper, pour order 68): 179.5,63.5 180.5,62.5 180.5,55 179.5,54 159.5,54 158.5,55 158.5,62.5 159.5,63.5
GND on Top Layer "GND_L02_P-001" (solid, remove dead copper, pour order 60): 136.5,25.5 137.5,26.5 142.5,26.5 143.5,25.5 143.5,5.5 142.667,4.5 137.5,4.5 136.5,5.5
24V_M5 on Top Layer "GND_L02_P-001" (solid, remove dead copper, pour order 59): 136,5.5 135,4.5 127.5,4.5 126.5,5.5 126.5,25.5 127.5,26.5 135,26.5 136,25.5
24V on Bottom Layer "GND_L02_P-001" (solid, remove dead copper, pour order 168): 133.75,131.25 136.25,133.75 136.25,156.5 137.5,157.75 140.25,157.75 141.5,156.5 141.5,116.5 135,110
24V on Bottom Layer "GND_L02_P-001" (solid, remove dead copper, pour order 167): 97,130 98.25,131.25 133.75,131.25 135,130 135,110 131.75,106.75 131.75,92 122.25,82.5 105.75,82.5 103,79.75 87.75,79.75 86.25,81.25 86.25,112.5 87.5,113.75 95.5,113.75 97,115.25
GND on Bottom Layer "GND_L02_P-001" (solid, remove dead copper, pour order 166): 98.25,132.5 97,133.75 97,153.75 98.5,155.25 133.75,155.25 135,154 135,133.75 133.75,132.5
24V_M4 on Bottom Layer "GND_L02_P-001" (solid, remove dead copper, pour order 64): 179.5,25 180.5,24 180.5,16.5 179.5,15.5 159.5,15.5 158.5,16.5 158.5,24 159.5,25
24V_M3 on Bottom Layer "GND_L02_P-001" (solid, remove dead copper, pour order 67): 179.5,44.25 180.5,43.25 180.5,35.75 179.5,34.75 159.5,34.75 158.5,35.75 158.5,43.25 159.5,44.25
GND on Bottom Layer "GND_L02_P-001" (solid, remove dead copper, pour order 96): 159.5,25.5 158.5,26.5 158.5,31.5 159.5,32.5 179.5,32.5 180.5,31.667 180.5,26.5 179.5,25.5
GND on Bottom Layer "GND_L02_P-001" (solid, remove dead copper, pour order 97): 159.5,44.75 158.5,45.75 158.5,50.75 159.5,51.75 179.5,51.75 180.5,50.917 180.5,45.75 179.5,44.75
24V_CHASSIS_F on Bottom Layer "GND_L02_P-001" (solid, remove dead copper, pour order 156): 129.75,67.25 129.25,67.75 127.25,67.75 122.5,72.5 122.5,77.75 121.75,78.5 106.75,78.5 106,77.75 106,57.5 107.5,56 129.25,56 129.75,56.5
24V_MISC_F on Bottom Layer "GND_L02_P-001" (solid, remove dead copper, pour order 152): 78.5,69 70,69 67.5,71.5 67.5,88.75 68.75,90 82.5,90 83.75,88.75 83.75,74.25
24V_ARM_F on Bottom Layer "GND_L02_P-001" (solid, remove dead copper, pour order 150): 75.75,135.5 79,138.75 95,138.75 96.25,137.5 96.25,119 95,117.5 77.25,117.5 75.75,119
24V_ARM_S on Bottom Layer "GND_L02_P-001" (solid, remove dead copper, pour order 148): 52.5,92.5 54,91 67.5,91 69,92.5 69,118.75 70.75,120.5 74.5,120.5 75.25,121.25 75.25,128.5 65,138.75 54.5,138.75 52.5,136.75 52.5,116.5 55,114 55,110.75 52.5,108.25
24V_CHASSIS_S on Bottom Layer "GND_L02_P-001" (solid, remove dead copper, pour order 145): 130.25,52.5 127.75,50 127.75,35.5 129.25,34 150.75,34 152.25,35 151.75,102.5 150.75,103.5 142.75,103.5 141.25,102 141.25,69 140,67.75 130.75,67.75 130.25,67.25
24V_CHASSIS_S on Bottom Layer "GND_L02_P-001" (solid, remove dead copper, pour order 146): 152.25,35 152.25,18 151.25,17 146.25,17 145.25,18 145.25,33 143.25,35 143,35
24V_MISC_S on Bottom Layer "GND_L02_P-001" (solid, remove dead copper, pour order 144): 33.75,35 33.75,17.25 35,16 41.5,16 42.75,17.25 42.75,32.75 45,35
24V_MISC_S on Bottom Layer "GND_L02_P-001" (solid, remove dead copper, pour order 143): 113.25,33.75 35,33.75 33.75,35 33.75,84
24V_MISC_S on Bottom Layer "GND_L02_P-001" (solid, remove dead copper, pour order 142): 33.75,84 34.75,85 52,85 68.5,68.5 78.5,68.5 79,68 79,62.5 89,52.5 112,52.5 113.75,50.75 113.75,34.25 113.25,33.75
24V_ARM1 on Bottom Layer "GND_L02_P-001" (solid, remove dead copper, pour order 108): 10.5,138 9,136.5 9,123.5 10.5,122 46.5,122 48,123.5 48,136.5 46.5,138
GND on Bottom Layer "GND_L02_P-001" (solid, remove dead copper, pour order 109): 10.5,138.5 9,140 9,147 10.5,148.5 46.5,148.5 48,147 48,140 46.5,138.5
GND on Bottom Layer "GND_L02_P-001" (solid, remove dead copper, pour order 105): 10.5,107.5 9,109 9,116 10.5,117.5 46.5,117.5 48,116 48,109 46.5,107.5
24V_ARM2 on Bottom Layer "GND_L02_P-001" (solid, remove dead copper, pour order 104): 10.5,107 9,105.5 9,92.5 10.5,91 46.5,91 48,92.5 48,105.5 46.5,107
GND on Bottom Layer "GND_L02_P-001" (solid, remove dead copper, pour order 94): 113.5,25.5 114.5,26.5 119.5,26.5 120.5,25.5 120.5,5.5 119.667,4.5 114.5,4.5 113.5,5.5
GND on Bottom Layer "GND_L02_P-001" (solid, remove dead copper, pour order 93): 94.5,25.5 95.5,26.5 100.5,26.5 101.5,25.5 101.5,5.5 100.667,4.5 95.5,4.5 94.5,5.5
GND on Bottom Layer "GND_L02_P-001" (solid, remove dead copper, pour order 92): 75.5,25.5 76.5,26.5 81.5,26.5 82.5,25.5 82.5,5.5 81.667,4.5 76.5,4.5 75.5,5.5
GND on Bottom Layer "GND_L02_P-001" (solid, remove dead copper, pour order 90): 56.5,25.5 57.5,26.5 62.5,26.5 63.5,25.5 63.5,5.5 62.667,4.5 57.5,4.5 56.5,5.5
24V_SPARE_1 on Bottom Layer "GND_L02_P-001" (solid, remove dead copper, pour order 58): 113,5.5 112,4.5 104.5,4.5 103.5,5.5 103.5,25.5 104.5,26.5 112,26.5 113,25.5
24V_SPARE_2 on Bottom Layer "GND_L02_P-001" (solid, remove dead copper, pour order 55): 94,5.5 93,4.5 85.5,4.5 84.5,5.5 84.5,25.5 85.5,26.5 93,26.5 94,25.5
24V_SPARE_3 on Bottom Layer "GND_L02_P-001" (solid, remove dead copper, pour order 52): 75,5.5 74,4.5 66.5,4.5 65.5,5.5 65.5,25.5 66.5,26.5 74,26.5 75,25.5
24V_SPARE_4 on Bottom Layer "GND_L02_P-001" (solid, remove dead copper, pour order 49): 56,5.5 55,4.5 47.5,4.5 46.5,5.5 46.5,25.5 47.5,26.5 55,26.5 56,25.5
24V_PoE on Bottom Layer "GND_L02_P-001" (solid, remove dead copper, pour order 32): 5.475,75.5 4.475,76.5 4.475,84 5.475,85 25.475,85 26.475,84 26.475,76.5 25.475,75.5
24V_SCIENCE on Bottom Layer "GND_L02_P-001" (solid, remove dead copper, pour order 79): 5.475,56.5 4.475,57.5 4.475,65 5.475,66 25.475,66 26.475,65 26.475,57.5 25.475,56.5
24V_LIGTHING on Bottom Layer "GND_L02_P-001" (solid, remove dead copper, pour order 82): 5.475,37.5 4.475,38.5 4.475,46 5.475,47 25.475,47 26.475,46 26.475,38.5 25.475,37.5
24V_SPARE_5 on Bottom Layer "GND_L02_P-001" (solid, remove dead copper, pour order 85): 5.475,18.5 4.475,19.5 4.475,27 5.475,28 25.475,28 26.475,27 26.475,19.5 25.475,18.5
GND on Bottom Layer "GND_L02_P-001" (solid, remove dead copper, pour order 86): 25.475,75 26.475,74 26.475,69 25.475,68 5.475,68 4.475,68.833 4.475,74 5.475,75
GND on Bottom Layer "GND_L02_P-001" (solid, remove dead copper, pour order 87): 25.475,56 26.475,55 26.475,50 25.475,49 5.475,49 4.475,49.833 4.475,55 5.475,56
GND on Bottom Layer "GND_L02_P-001" (solid, remove dead copper, pour order 88): 25.475,37 26.475,36 26.475,31 25.475,30 5.475,30 4.475,30.833 4.475,36 5.475,37
GND on Bottom Layer "GND_L02_P-001" (solid, remove dead copper, pour order 89): 25.475,18 26.475,17 26.475,12 25.475,11 5.475,11 4.475,11.833 4.475,17 5.475,18
GND on Bottom Layer "GND_L02_P-001" (solid, remove dead copper, pour order 100): 159.5,102 158.5,103 158.5,108 159.5,109 179.5,109 180.5,108.167 180.5,103 179.5,102
GND on Bottom Layer "GND_L02_P-001" (solid, remove dead copper, pour order 99): 159.5,83 158.5,84 158.5,89 159.5,90 179.5,90 180.5,89.167 180.5,84 179.5,83
GND on Bottom Layer "GND_L02_P-001" (solid, remove dead copper, pour order 98): 159.5,64 158.5,65 158.5,70 159.5,71 179.5,71 180.5,70.167 180.5,65 179.5,64
GND on Bottom Layer "GND_L02_P-001" (solid, remove dead copper, pour order 95): 136.5,25.5 137.5,26.5 142.5,26.5 143.5,25.5 143.5,5.5 142.667,4.5 137.5,4.5 136.5,5.5
24V_M0 on Bottom Layer "GND_L02_P-001" (solid, remove dead copper, pour order 76): 179.5,101.5 180.5,100.5 180.5,93 179.5,92 159.5,92 158.5,93 158.5,100.5 159.5,101.5
24V_M1 on Bottom Layer "GND_L02_P-001" (solid, remove dead copper, pour order 73): 179.5,82.5 180.5,81.5 180.5,74 179.5,73 159.5,73 158.5,74 158.5,81.5 159.5,82.5
24V_M2 on Bottom Layer "GND_L02_P-001" (solid, remove dead copper, pour order 70): 179.5,63.5 180.5,62.5 180.5,55 179.5,54 159.5,54 158.5,55 158.5,62.5 159.5,63.5
24V_M5 on Bottom Layer "GND_L02_P-001" (solid, remove dead copper, pour order 61): 136,5.5 135,4.5 127.5,4.5 126.5,5.5 126.5,25.5 127.5,26.5 135,26.5 136,25.5
GND on Int1 (GND) "GND_L02_P-001" (solid, remove dead copper, pour order 33): 0,0 0,160 185,160 185,0
GND on Int2 (GND) "GND_L02_P-001" (solid, remove dead copper, pour order 34): 0,0 0,160 185,160 185,0

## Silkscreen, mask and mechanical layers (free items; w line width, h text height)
Top Overlay:
  drawing of 20 lines, arcs and shapes, not listed
  text "GND" at 109.552,152.787 h4 r180
  text "GND" at 130.376,152.787 h4 r180
  text "CAN FD" at 178.544,150.938 h2 r270
  text "CAN FD" at 178.544,142.188 h2 r270
  text "+" at 0.754,124.671 h2
  text "24V ARM" at 12.6,124.433 h3 r180
  text "TX" at 178.45,122.8 h1 r270
  text "PDB2 UART" at 174.149,122.437 h2 r270
  text "SWCLK" at 160.283,120.679 h2 r270
  text "SWDIO" at 162.783,120.679 h2 r270
  text "NRST" at 157.533,119.225 h2 r270
  text "RX" at 178.45,118.55 h1 r270
  text "3.3V" at 165.283,118 h2 r270
  text "GND" at 167.783,118 h2 r270
  text "TX" at 178.45,115.8 h1 r270
  text "PDB3 UART" at 174.149,115.437 h2 r270
  text "24V VBAT" at 113.854,114.037 h4 r180
  text "24V VBAT" at 134.604,114.037 h4 r180
  text "RX" at 178.45,111.55 h1 r270
  text "BOOT0" at 147.724,109.717 h2 r180
  text "NRST" at 154.225,109.717 h2 r180
  text "+" at 0.754,94.171 h2
  text "24V ARM" at 12.6,93.433 h3 r180
  text "+" at 182.504,92.671 h2
  text "24V" at 184.375,92.433 h3 r180
  text "+" at 1.254,82.421 h2
  text "+" at 182.504,73.671 h2
  text "24V" at 184.125,73.433 h3 r180
  text "24V" at 6.75,68.456 h3 r180
  text "+" at 1.451,63.309 h2
  text "+" at 182.254,54.671 h2
  text "24V" at 184.125,54.183 h3 r180
  text "24V" at 6.796,49.456 h3 r180
  text "+" at 1.226,44.309 h2
  text "+" at 182.504,35.421 h2
  text "24V" at 184.125,35.183 h3 r180
  text "24V" at 6.796,30.456 h3 r180
  text "+" at 1.226,25.309 h2
  text "+" at 182.476,16.06 h2
  text "24V" at 184.125,15.183 h3 r180
  text "24V" at 6.75,11.206 h3 r180
  text "Designed by: Rishi Upath & Lochlan Rode" at 46,8.339 h2 r180
  text "24V" at 120.071,6.905 h3 r270
  text "24V" at 143.321,6.905 h3 r270
  text "24V" at 82.067,6.826 h3 r270
  text "24V" at 101.067,6.826 h3 r270
  text "24V" at 63.067,6.75 h3 r270
  text "PDB1 | REV 1.0 | July 2026" at 46,5.479 h2.5 r180
  text "24V 20A PDB" at 46,3.217 h3 r180
  text "+" at 66.476,1.06 h2
  text "+" at 47.476,0.81 h2
  text "+" at 85.476,0.81 h2
  text "+" at 104.476,0.81 h2
  text "+" at 127.476,0.81 h2
Mechanical 1:
  lines w0.254: 9.414,0 182.586,0 ; 185,3.414 cw(c181.586,3.414) 181.519,0.001 cw(c181.519,0.001) 181.519,0 3.414,0 cw(c3.414,3.414) 0,3.414 0,156.586 cw(c3.414,156.586) 3.414,160 181.586,160 cw(c181.586,156.586) 185,156.586 ; 185,3.664 185,156.836 ; 185,4.414 185,157.586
